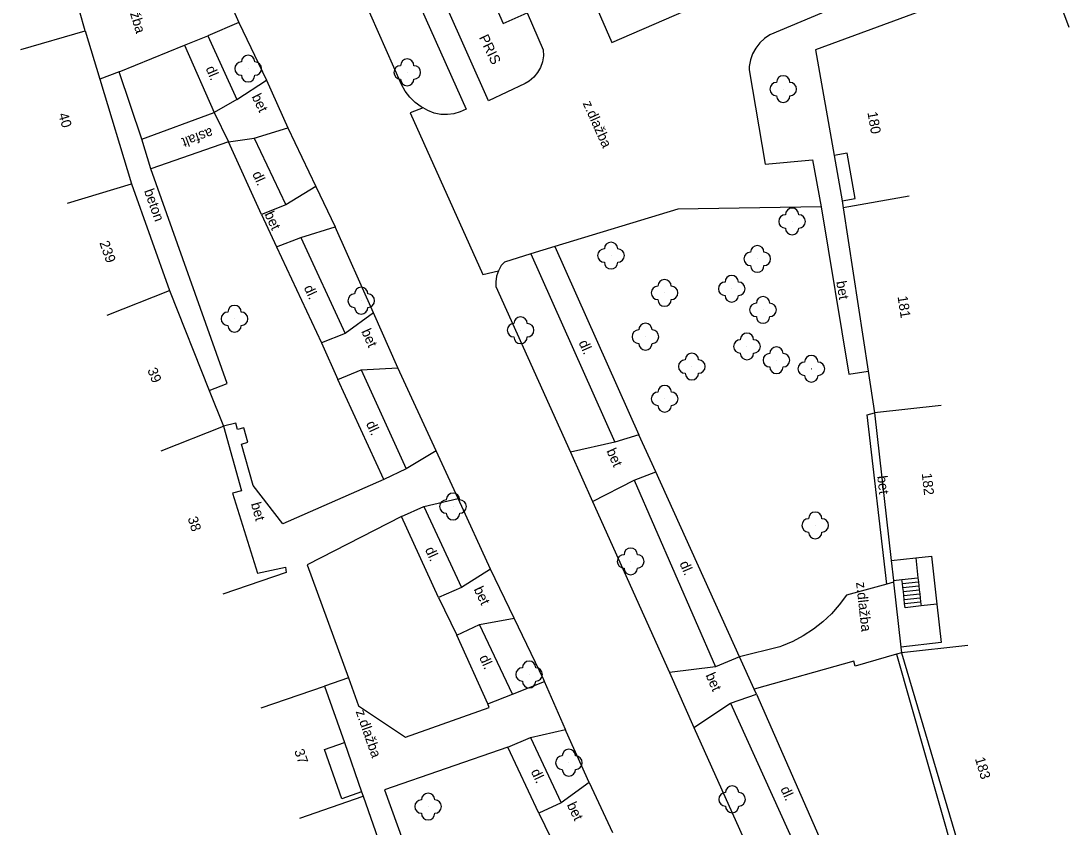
# Model space of a CAD drawing. Extents: x -544674 to -541478, y -1199076 to -1195527.
# Drawn here: x -542613.8 to -542535.4, y -1198743.1 to -1198682.9 of the extents above; entities that cross this region are included whole.
import ezdxf

# ---------------------------------------------------------------- set-up
doc = ezdxf.new("R2010")
doc.units = 0
for name, color, linetype in [('BUDOVY_MĚŘ', 7, 'Continuous'), ('POMOC_POPIS', 7, 'Continuous'), ('ROZHRANÍ_PLOCH', 7, 'Continuous'), ('ZELEŇ', 7, 'Continuous'), ('Č_POPIS_ORIENT', 7, 'Continuous')]:
    doc.layers.add(name, color=color, linetype=linetype)

msp = doc.modelspace()

# ---------------------------------------------------------------- linework, layer by layer
at = {"layer": 'BUDOVY_MĚŘ'}
for points in [[(-542537.17, -1198678.72), (-542554.38, -1198685.06), (-542553, -1198692.95)], [(-542535.44, -1198683.41), (-542537.17, -1198678.72)], [(-542608.97, -1198683.64), (-542609.4, -1198682.16)], [(-542613.77, -1198685.05), (-542608.97, -1198683.64)], [(-542608.97, -1198683.64), (-542607.87, -1198687.25)], [(-542607.87, -1198687.25), (-542605.5, -1198695.08)], [(-542553, -1198692.95), (-542552.4, -1198696.35)], [(-542610.29, -1198696.53), (-542605.5, -1198695.08)], [(-542605.5, -1198695.08), (-542602.67, -1198703.04)], [(-542552.4, -1198696.35), (-542552.31, -1198696.87)], [(-542547.39, -1198696.01), (-542552.31, -1198696.87)], [(-542552.31, -1198696.87), (-542550.45, -1198709.08)], [(-542607.32, -1198704.89), (-542602.67, -1198703.04)], [(-542602.67, -1198703.04), (-542599.7, -1198710.52)], [(-542550.45, -1198709.08), (-542549.97, -1198712.2)], [(-542599.7, -1198710.52), (-542598.64, -1198713.19)], [(-542545, -1198711.65), (-542549.97, -1198712.2)], [(-542549.97, -1198712.2), (-542548.74, -1198723.23)], [(-542603.29, -1198715.03), (-542598.64, -1198713.19)], [(-542598.64, -1198713.19), (-542597.3, -1198718.01), (-542597.97, -1198718.2), (-542596.1, -1198724.16), (-542594.01, -1198723.71), (-542593.95, -1198724.13), (-542598.69, -1198725.73)], [(-542548.74, -1198723.23), (-542548.57, -1198724.72)], [(-542548.57, -1198724.72), (-542548.56, -1198724.85)], [(-542548.56, -1198724.85), (-542548.01, -1198729.7)], [(-542548.01, -1198729.7), (-542547.97, -1198730.12)], [(-542543, -1198729.57), (-542547.97, -1198730.12)], [(-542547.97, -1198730.12), (-542542.37, -1198748.94)], [(-542595.82, -1198734.22), (-542591.08, -1198732.62)], [(-542591.08, -1198732.62), (-542589.6, -1198736.83)], [(-542588.31, -1198740.51), (-542589.8, -1198741.03), (-542591.09, -1198737.35), (-542589.6, -1198736.83)], [(-542589.6, -1198736.83), (-542588.31, -1198740.51)], [(-542592.92, -1198742.48), (-542588.2, -1198740.82)], [(-542588.31, -1198740.51), (-542588.2, -1198740.82)], [(-542588.2, -1198740.82), (-542585.22, -1198749.33)]]:
    msp.add_lwpolyline(points, dxfattribs=at)
at = {"layer": 'ROZHRANÍ_PLOCH'}
for points in [[(-542592.24, -1198627.07), (-542594.07, -1198627.92), (-542588.53, -1198640.99), (-542578.92, -1198663.12), (-542569.62, -1198684.53), (-542553.23, -1198677.4)], [(-542575.94, -1198682.29), (-542574.73, -1198685.07), (-542574.72, -1198685.52), (-542574.79, -1198685.96), (-542574.94, -1198686.38), (-542575.16, -1198686.77), (-542575.45, -1198687.11), (-542575.79, -1198687.4), (-542576.08, -1198687.57), (-542578.84, -1198688.88), (-542586.62, -1198671.35), (-542592.44, -1198658.01), (-542589.29, -1198656.7), (-542588.09, -1198659.31), (-542586.31, -1198658.53), (-542577.52, -1198678.62), (-542579.32, -1198679.43), (-542577.73, -1198683.09), (-542575.94, -1198682.29)], [(-542588.91, -1198670.68), (-542580.49, -1198689.5), (-542580.94, -1198689.71), (-542581.41, -1198689.85), (-542581.9, -1198689.91), (-542582.4, -1198689.89), (-542582.88, -1198689.79), (-542583.35, -1198689.61), (-542583.7, -1198689.41)], [(-542583.7, -1198689.41), (-542583.85, -1198689.32), (-542584.3, -1198688.99), (-542584.71, -1198688.6), (-542585.05, -1198688.15), (-542585.33, -1198687.66), (-542588.78, -1198679.86), (-542590.79, -1198675.21)], [(-542598.72, -1198680.26), (-542597.49, -1198683.03)], [(-542551.63, -1198681.36), (-542557.79, -1198683.94), (-542558.2, -1198684.21), (-542558.56, -1198684.54), (-542558.86, -1198684.93), (-542559.09, -1198685.36), (-542559.25, -1198685.82), (-542559.34, -1198686.3), (-542559.35, -1198686.55), (-542558.15, -1198693.6), (-542554.61, -1198693.29), (-542553.96, -1198696.79)], [(-542597.49, -1198683.03), (-542599.81, -1198684.02)], [(-542597.49, -1198683.03), (-542595.42, -1198687.34)], [(-542606.42, -1198686.71), (-542601.55, -1198684.73)], [(-542601.55, -1198684.73), (-542599.81, -1198684.02)], [(-542601.55, -1198684.73), (-542599.32, -1198689.75)], [(-542599.81, -1198684.02), (-542597.64, -1198688.77)], [(-542606.42, -1198686.71), (-542607.87, -1198687.25)], [(-542604.74, -1198691.75), (-542606.42, -1198686.71)], [(-542597.64, -1198688.77), (-542595.42, -1198687.34)], [(-542595.42, -1198687.34), (-542593.82, -1198690.9)], [(-542597.64, -1198688.77), (-542599.32, -1198689.75)], [(-542583.7, -1198689.41), (-542584.68, -1198689.78), (-542579.25, -1198701.86), (-542578.07, -1198701.57)], [(-542604.74, -1198691.75), (-542599.32, -1198689.75)], [(-542599.32, -1198689.75), (-542598.25, -1198691.94)], [(-542596.33, -1198691.66), (-542593.82, -1198690.9)], [(-542593.82, -1198690.9), (-542591.72, -1198695.28)], [(-542604.06, -1198693.97), (-542604.74, -1198691.75)], [(-542598.25, -1198691.94), (-542596.33, -1198691.66)], [(-542596.33, -1198691.66), (-542593.97, -1198696.65)], [(-542598.25, -1198691.94), (-542604.06, -1198693.97)], [(-542595.79, -1198697.37), (-542598.25, -1198691.94)], [(-542552.4, -1198696.35), (-542551.42, -1198696.18), (-542552.01, -1198692.78), (-542553, -1198692.95)], [(-542599.7, -1198710.52), (-542598.35, -1198709.99), (-542604.06, -1198693.97)], [(-542591.72, -1198695.28), (-542593.97, -1198696.65)], [(-542591.72, -1198695.28), (-542590.28, -1198698.28)], [(-542593.97, -1198696.65), (-542595.79, -1198697.37)], [(-542553.96, -1198696.79), (-542564.67, -1198696.98), (-542573.87, -1198699.77)], [(-542553.96, -1198696.79), (-542551.9, -1198709.3), (-542550.45, -1198709.08)], [(-542595.79, -1198697.37), (-542594.67, -1198699.78)], [(-542592.86, -1198699.09), (-542590.28, -1198698.28)], [(-542587.42, -1198704.73), (-542590.28, -1198698.28)], [(-542594.67, -1198699.78), (-542592.86, -1198699.09)], [(-542592.86, -1198699.09), (-542589.55, -1198706.26)], [(-542594.67, -1198699.78), (-542591.31, -1198706.96)], [(-542575.66, -1198700.32), (-542577.64, -1198700.94), (-542577.87, -1198701.19), (-542578.04, -1198701.49), (-542578.07, -1198701.57)], [(-542573.87, -1198699.77), (-542575.66, -1198700.32)], [(-542575.66, -1198700.32), (-542569.39, -1198714.39)], [(-542573.87, -1198699.77), (-542567.6, -1198713.83)], [(-542578.07, -1198701.57), (-542578.22, -1198701.98), (-542578.29, -1198702.41), (-542578.29, -1198702.76), (-542572.71, -1198715.13)], [(-542587.42, -1198704.73), (-542589.55, -1198706.26)], [(-542585.61, -1198708.82), (-542587.42, -1198704.73)], [(-542589.55, -1198706.26), (-542591.31, -1198706.96)], [(-542591.31, -1198706.96), (-542590.08, -1198709.71)], [(-542590.08, -1198709.71), (-542588.35, -1198708.97)], [(-542588.35, -1198708.97), (-542585.61, -1198708.82)], [(-542588.35, -1198708.97), (-542584.97, -1198716.38)], [(-542582.74, -1198715.02), (-542585.61, -1198708.82)], [(-542586.66, -1198717.16), (-542590.08, -1198709.71)], [(-542586.66, -1198717.16), (-542594.21, -1198720.49), (-542596.42, -1198717.63), (-542597.29, -1198714.52), (-542596.82, -1198714.39), (-542597.11, -1198713.3), (-542597.59, -1198713.43), (-542597.72, -1198712.97), (-542598.64, -1198713.19)], [(-542549.05, -1198724.98), (-542550.52, -1198712.34), (-542549.97, -1198712.2)], [(-542569.39, -1198714.39), (-542572.71, -1198715.13)], [(-542567.6, -1198713.83), (-542569.39, -1198714.39)], [(-542566.33, -1198716.61), (-542567.6, -1198713.83)], [(-542582.74, -1198715.02), (-542584.97, -1198716.38)], [(-542581.1, -1198718.59), (-542582.74, -1198715.02)], [(-542572.71, -1198715.13), (-542571.06, -1198718.81)], [(-542584.97, -1198716.38), (-542586.66, -1198717.16)], [(-542567.95, -1198717.21), (-542566.33, -1198716.61)], [(-542560.07, -1198730.42), (-542566.33, -1198716.61)], [(-542571.06, -1198718.81), (-542567.95, -1198717.21)], [(-542567.95, -1198717.21), (-542561.87, -1198731.17)], [(-542585.32, -1198719.94), (-542583.66, -1198719.19)], [(-542583.66, -1198719.19), (-542581.1, -1198718.59)], [(-542583.66, -1198719.19), (-542580.84, -1198725.23)], [(-542578.68, -1198723.88), (-542581.1, -1198718.59)], [(-542571.06, -1198718.81), (-542565.3, -1198731.58)], [(-542585.32, -1198719.94), (-542592.37, -1198723.55), (-542589.3, -1198731.98)], [(-542582.57, -1198725.99), (-542585.32, -1198719.94)], [(-542548.74, -1198723.23), (-542546.9, -1198723.03)], [(-542546.9, -1198723.03), (-542545.71, -1198722.9), (-542545.31, -1198726.48)], [(-542546.9, -1198723.03), (-542546.73, -1198724.52)], [(-542578.68, -1198723.88), (-542580.84, -1198725.23)], [(-542576.92, -1198727.53), (-542578.68, -1198723.88)], [(-542548.57, -1198724.72), (-542547.93, -1198724.65)], [(-542547.93, -1198724.65), (-542546.73, -1198724.52)], [(-542547.89, -1198724.95), (-542547.93, -1198724.65)], [(-542546.73, -1198724.52), (-542546.7, -1198724.82)], [(-542580.84, -1198725.23), (-542582.57, -1198725.99)], [(-542549.05, -1198724.98), (-542552.08, -1198725.81), (-542552.61, -1198726.53), (-542553.2, -1198727.2), (-542553.85, -1198727.81), (-542554.55, -1198728.36), (-542555.3, -1198728.85), (-542556.09, -1198729.27), (-542556.92, -1198729.62), (-542557.06, -1198729.67), (-542560.07, -1198730.42)], [(-542548.56, -1198724.85), (-542549.05, -1198724.98)], [(-542547.89, -1198724.95), (-542546.7, -1198724.82)], [(-542547.86, -1198725.25), (-542547.89, -1198724.95)], [(-542547.86, -1198725.25), (-542546.67, -1198725.12)], [(-542547.82, -1198725.55), (-542547.86, -1198725.25)], [(-542547.82, -1198725.55), (-542546.64, -1198725.41)], [(-542546.7, -1198724.82), (-542546.67, -1198725.12)], [(-542546.67, -1198725.12), (-542546.64, -1198725.41)], [(-542546.64, -1198725.41), (-542546.6, -1198725.71)], [(-542582.57, -1198725.99), (-542581.2, -1198728.8)], [(-542547.79, -1198725.84), (-542547.82, -1198725.55)], [(-542547.79, -1198725.84), (-542546.6, -1198725.71)], [(-542547.76, -1198726.14), (-542547.79, -1198725.84)], [(-542547.76, -1198726.14), (-542546.57, -1198726.01)], [(-542547.73, -1198726.44), (-542547.76, -1198726.14)], [(-542546.6, -1198725.71), (-542546.57, -1198726.01)], [(-542546.57, -1198726.01), (-542546.54, -1198726.31)], [(-542545.31, -1198726.48), (-542544.99, -1198729.36), (-542548.01, -1198729.7)], [(-542547.73, -1198726.44), (-542546.54, -1198726.31)], [(-542546.5, -1198726.62), (-542547.69, -1198726.75), (-542547.73, -1198726.44)], [(-542546.54, -1198726.31), (-542546.5, -1198726.62)], [(-542545.31, -1198726.48), (-542546.5, -1198726.62)], [(-542579.5, -1198728.01), (-542576.92, -1198727.53)], [(-542574.64, -1198732.26), (-542574.7, -1198732.13), (-542576.92, -1198727.53)], [(-542581.2, -1198728.8), (-542579.5, -1198728.01)], [(-542577.04, -1198733.21), (-542579.5, -1198728.01)], [(-542578.88, -1198733.93), (-542581.2, -1198728.8)], [(-542547.97, -1198730.12), (-542548.33, -1198730.23)], [(-542560.07, -1198730.42), (-542561.87, -1198731.17)], [(-542558.98, -1198732.83), (-542560.07, -1198730.42)], [(-542548.33, -1198730.23), (-542551.43, -1198731.13), (-542551.52, -1198730.75), (-542558.98, -1198732.83)], [(-542548.33, -1198730.23), (-542544.04, -1198745.26)], [(-542561.87, -1198731.17), (-542565.3, -1198731.58)], [(-542565.3, -1198731.58), (-542563.49, -1198735.71)], [(-542589.3, -1198731.98), (-542591.08, -1198732.62)], [(-542589.3, -1198731.98), (-542588.54, -1198734.08), (-542585.04, -1198736.43), (-542578.79, -1198734.2), (-542578.88, -1198733.93)], [(-542577.04, -1198733.21), (-542574.64, -1198732.26)], [(-542573.08, -1198735.86), (-542574.64, -1198732.26)], [(-542578.88, -1198733.93), (-542577.04, -1198733.21)], [(-542560.74, -1198733.88), (-542558.81, -1198733.2)], [(-542558.81, -1198733.2), (-542558.98, -1198732.83)], [(-542558.81, -1198733.2), (-542552.17, -1198748.31)], [(-542563.49, -1198735.71), (-542560.74, -1198733.88)], [(-542560.74, -1198733.88), (-542553.91, -1198748.94)], [(-542577.39, -1198737.16), (-542575.68, -1198736.45)], [(-542575.68, -1198736.45), (-542573.08, -1198735.86)], [(-542575.68, -1198736.45), (-542573.4, -1198741.33)], [(-542571.3, -1198739.8), (-542573.02, -1198736), (-542573.08, -1198735.86)], [(-542563.49, -1198735.71), (-542557.21, -1198749.67)], [(-542577.39, -1198737.16), (-542586.61, -1198740.35), (-542580.5, -1198757.23)], [(-542575.06, -1198742.1), (-542577.39, -1198737.16)], [(-542571.3, -1198739.8), (-542573.4, -1198741.33)], [(-542571.3, -1198739.8), (-542569.57, -1198743.55)], [(-542573.4, -1198741.33), (-542575.06, -1198742.1)], [(-542575.06, -1198742.1), (-542573.72, -1198744.87)]]:
    msp.add_lwpolyline(points, dxfattribs=at)
at = {"layer": 'ZELEŇ'}
for centre in [(-542596.79, -1198686.47), (-542584.9, -1198686.75), (-542556.8, -1198688), (-542556.14, -1198697.89), (-542569.67, -1198700.44), (-542558.74, -1198700.69), (-542565.67, -1198703.23), (-542560.65, -1198702.92), (-542588.34, -1198703.81), (-542558.31, -1198704.5), (-542597.81, -1198705.16), (-542576.43, -1198706.02), (-542567.1, -1198706.5), (-542559.51, -1198707.23), (-542557.31, -1198708.26), (-542563.63, -1198708.73), (-542554.7, -1198708.9), (-542565.66, -1198711.14), (-542581.48, -1198719.19), (-542554.41, -1198720.6), (-542568.2, -1198723.29), (-542575.79, -1198731.74), (-542572.82, -1198738.33), (-542560.62, -1198741.07), (-542583.34, -1198741.61)]:
    msp.add_circle(centre, 0.0005, dxfattribs=at)
for centre, start, end in [((-542596.79, -1198685.97), 0, 179.99999), ((-542597.29, -1198686.47), 89.99999, 269.99999), ((-542596.29, -1198686.47), 270, 89.99999), ((-542585.4, -1198686.75), 89.99999, 269.99999), ((-542584.9, -1198686.25), 0, 179.99999), ((-542584.4, -1198686.75), 270, 89.99999), ((-542596.79, -1198686.97), 179.99999, 359.99999), ((-542556.8, -1198687.5), 0, 179.99999), ((-542584.9, -1198687.25), 179.99999, 359.99999), ((-542557.3, -1198688), 89.99999, 269.99999), ((-542556.3, -1198688), 270, 89.99999), ((-542556.8, -1198688.5), 179.99999, 359.99999), ((-542556.14, -1198697.39), 0, 179.99999), ((-542556.64, -1198697.89), 89.99999, 269.99999), ((-542555.64, -1198697.89), 270, 89.99999), ((-542556.14, -1198698.39), 179.99999, 359.99999), ((-542569.67, -1198699.94), 0, 179.99999), ((-542570.17, -1198700.44), 89.99999, 269.99999), ((-542569.17, -1198700.44), 270, 89.99999), ((-542559.24, -1198700.69), 89.99999, 269.99999), ((-542558.74, -1198700.19), 0, 179.99999), ((-542558.24, -1198700.69), 270, 89.99999), ((-542569.67, -1198700.94), 179.99999, 359.99999), ((-542558.74, -1198701.19), 179.99999, 359.99999), ((-542560.65, -1198702.42), 0, 179.99999), ((-542566.17, -1198703.23), 89.99999, 269.99999), ((-542565.67, -1198702.73), 0, 179.99999), ((-542565.17, -1198703.23), 270, 89.99999), ((-542561.15, -1198702.92), 89.99999, 269.99999), ((-542560.15, -1198702.92), 270, 89.99999), ((-542588.84, -1198703.81), 89.99999, 269.99999), ((-542588.34, -1198703.31), 0, 179.99999), ((-542587.84, -1198703.81), 270, 89.99999), ((-542560.65, -1198703.42), 179.99999, 359.99999), ((-542558.31, -1198704), 0, 179.99999), ((-542597.81, -1198704.66), 0, 179.99999), ((-542588.34, -1198704.31), 179.99999, 359.99999), ((-542565.67, -1198703.73), 179.99999, 359.99999), ((-542558.81, -1198704.5), 89.99999, 269.99999), ((-542557.81, -1198704.5), 270, 89.99999), ((-542598.31, -1198705.16), 89.99999, 269.99999), ((-542597.31, -1198705.16), 270, 89.99999), ((-542576.43, -1198705.52), 0, 179.99999), ((-542558.31, -1198705), 179.99999, 359.99999), ((-542597.81, -1198705.66), 179.99999, 359.99999), ((-542576.93, -1198706.02), 89.99999, 269.99999), ((-542575.93, -1198706.02), 270, 89.99999), ((-542567.1, -1198706), 0, 179.99999), ((-542576.43, -1198706.52), 179.99999, 359.99999), ((-542567.6, -1198706.5), 89.99999, 269.99999), ((-542566.6, -1198706.5), 270, 89.99999), ((-542559.51, -1198706.73), 0, 179.99999), ((-542567.1, -1198707), 179.99999, 359.99999), ((-542560.01, -1198707.23), 89.99999, 269.99999), ((-542559.01, -1198707.23), 270, 89.99999), ((-542557.31, -1198707.76), 0, 179.99999), ((-542564.13, -1198708.73), 89.99999, 269.99999), ((-542563.63, -1198708.23), 0, 179.99999), ((-542563.13, -1198708.73), 270, 89.99999), ((-542559.51, -1198707.73), 179.99999, 359.99999), ((-542557.81, -1198708.26), 89.99999, 269.99999), ((-542556.81, -1198708.26), 270, 89.99999), ((-542554.7, -1198708.4), 0, 179.99999), ((-542557.31, -1198708.76), 179.99999, 359.99999), ((-542555.2, -1198708.9), 89.99999, 269.99999), ((-542554.2, -1198708.9), 270, 89.99999), ((-542563.63, -1198709.23), 179.99999, 359.99999), ((-542554.7, -1198709.4), 179.99999, 359.99999), ((-542565.66, -1198710.64), 0, 179.99999), ((-542566.16, -1198711.14), 89.99999, 269.99999), ((-542565.16, -1198711.14), 270, 89.99999), ((-542565.66, -1198711.64), 179.99999, 359.99999), ((-542581.48, -1198718.69), 0, 179.99999), ((-542581.98, -1198719.19), 89.99999, 269.99999), ((-542580.98, -1198719.19), 270, 89.99999), ((-542581.48, -1198719.69), 179.99999, 359.99999), ((-542554.41, -1198720.1), 0, 179.99999), ((-542554.91, -1198720.6), 89.99999, 269.99999), ((-542553.91, -1198720.6), 270, 89.99999), ((-542554.41, -1198721.1), 179.99999, 359.99999), ((-542568.2, -1198722.79), 0, 179.99999), ((-542568.7, -1198723.29), 89.99999, 269.99999), ((-542567.7, -1198723.29), 270, 89.99999), ((-542568.2, -1198723.79), 179.99999, 359.99999), ((-542575.79, -1198731.24), 0, 179.99999), ((-542576.29, -1198731.74), 89.99999, 269.99999), ((-542575.29, -1198731.74), 270, 89.99999), ((-542575.79, -1198732.24), 179.99999, 359.99999), ((-542573.32, -1198738.33), 89.99999, 269.99999), ((-542572.82, -1198737.83), 0, 179.99999), ((-542572.32, -1198738.33), 270, 89.99999), ((-542572.82, -1198738.83), 179.99999, 359.99999), ((-542560.62, -1198740.57), 0, 179.99999), ((-542583.84, -1198741.61), 89.99999, 269.99999), ((-542583.34, -1198741.11), 0, 179.99999), ((-542582.84, -1198741.61), 270, 89.99999), ((-542561.12, -1198741.07), 89.99999, 269.99999), ((-542560.12, -1198741.07), 270, 89.99999), ((-542560.62, -1198741.57), 179.99999, 359.99999), ((-542583.34, -1198742.11), 179.99999, 359.99999)]:
    msp.add_arc(centre, 0.5, start, end, dxfattribs=at)

# ---------------------------------------------------------------- texts
at = {"layer": 'POMOC_POPIS'}
for s, rotation, p in [('z.dlažba', 286.87, (-542606.24, -1198680.32)), ('PRIS', 295.74002, (-542579.56, -1198684.14)), ('dl.', 293.06001, (-542599.98, -1198686.45)), ('bet', 296.04002, (-542596.55, -1198688.56)), ('z.dlažba', 294.20002, (-542571.8, -1198689.06)), ('asfalt', 200.25001, (-542599.57, -1198690.86)), ('dl.', 294.37002, (-542596.5, -1198694.33)), ('beton', 289.57, (-542604.58, -1198695.6)), ('bet', 294.93003, (-542595.59, -1198697.34)), ('dl.', 295.08003, (-542592.65, -1198702.84)), ('bet', 279.34998, (-542552.84, -1198702.39)), ('bet', 294.09998, (-542588.35, -1198706.1)), ('dl.', 294.02, (-542572.11, -1198706.94)), ('dl.', 294.65999, (-542588, -1198712.99)), ('bet', 294.15, (-542570.03, -1198715.03)), ('bet', 276.64998, (-542549.78, -1198716.92)), ('bet', 285.53999, (-542596.59, -1198718.98)), ('dl.', 294.43997, (-542583.59, -1198722.4)), ('dl.', 293.53, (-542564.57, -1198723.44)), ('bet', 295.74998, (-542579.95, -1198725.37)), ('z.dlažba', 276.36997, (-542551.36, -1198724.86)), ('dl.', 294.33002, (-542579.54, -1198730.47)), ('bet', 293.66998, (-542562.62, -1198731.79)), ('z.dlažba', 289.34999, (-542588.76, -1198734.51)), ('dl.', 295.25002, (-542575.68, -1198738.99)), ('dl.', 294.39998, (-542557.03, -1198740.29)), ('bet', 295.82, (-542572.99, -1198741.48))]:
    msp.add_text(s, height=0.75, rotation=rotation, dxfattribs=at).set_placement(p)
at = {"layer": 'Č_POPIS_ORIENT'}
for s, rotation, p in [('40', 286.87, (-542610.99, -1198689.89)), ('180', 279.94002, (-542550.51, -1198689.75)), ('239', 289.57, (-542607.92, -1198699.48)), ('181', 278.68003, (-542548.26, -1198703.5)), ('39', 291.65998, (-542604.34, -1198708.99)), ('182', 276.36997, (-542546.45, -1198716.72)), ('38', 287.45, (-542601.32, -1198720.06)), ('37', 289.34999, (-542593.36, -1198737.45)), ('183', 286.58002, (-542542.48, -1198738.03))]:
    msp.add_text(s, height=0.75, rotation=rotation, dxfattribs=at).set_placement(p)

doc.saveas('drawing.dxf')
